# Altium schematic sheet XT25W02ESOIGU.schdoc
size 127 x 101 mm
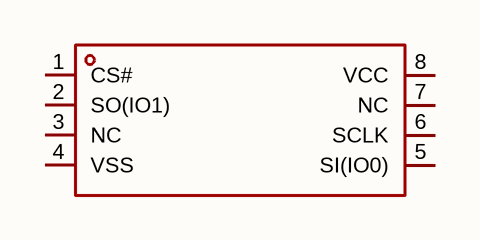
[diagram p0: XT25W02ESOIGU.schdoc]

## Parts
U?  xt25w02esoigu  [SO-8_L4.9-W3.9-P1.27-LS5.9-BL]  (value not drawn)

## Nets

Not connected (* = marked no-connect by the designer): U? 1(CS#) 2(SO(IO1)) 3(NC) 4(VSS) 5(SI(IO0)) 6(SCLK) 7(NC) 8(VCC)

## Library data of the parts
U? = xt25w02esoigu: 接口类型:SPI;存储容量:2Mbit;时钟频率(fc):60MHz;; Manufacturer: XTX(芯天下); AddInBom: yes; ModelId: 756fba4e187a48c69a2c935cd5c4465b; ModelName: SO-8_L4.9-W3.9-H1.5-LS5.9-P1.27; ModelTransform: 240.39054,192.913,0,270,0,0,0.0005,-0.0005,0; Interface Type: SPI; Memory Size: 2Mbit; Clock Frequency (fc): 60MHz; Supply Voltage: 1.65V~3.6V; Page Programming Time (Tpp): 2.5ms; Block Erase Time (tBE): 800ms; Data Retention - TDR (Year): 20年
